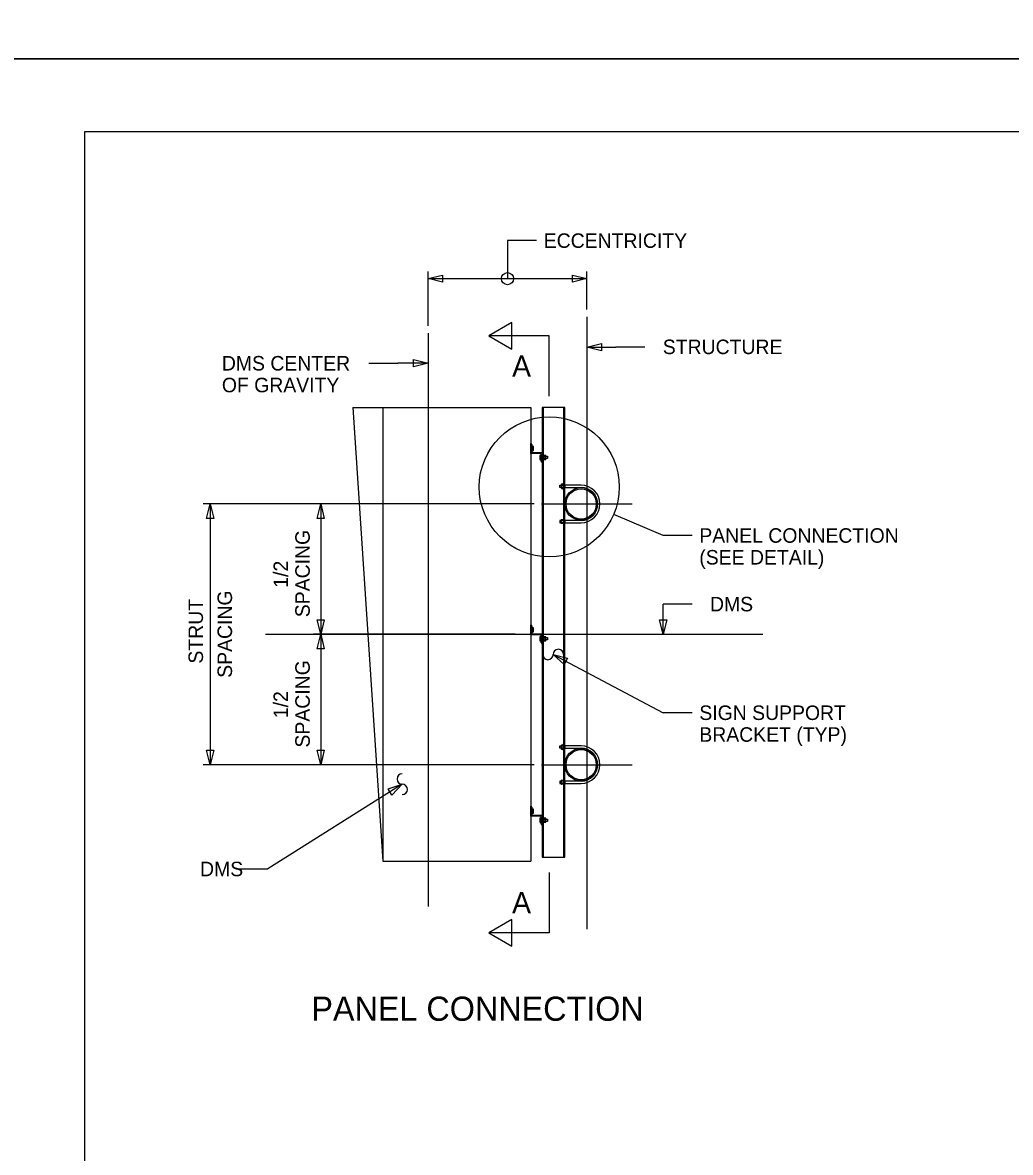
# Model space of a CAD drawing. Extents: x 3829340 to 3831660, y 499389 to 501171.
# Drawn here: x 3830208.1 to 3830412.4, y 499757.1 to 499990.7 of the extents above; entities that cross this region are included whole.
import ezdxf

# ---------------------------------------------------------------- set-up
doc = ezdxf.new("R2010")
doc.units = 0
for name, color, linetype in [('0-ANCHOR', 7, 'Continuous'), ('2', 7, 'Continuous'), ('CNTR', 7, 'Continuous'), ('Default', 7, 'Continuous'), ('DIM TXT', 7, 'Continuous'), ('PLT-BNDY', 7, 'Continuous'), ('sign', 7, 'Continuous'), ('structure', 7, 'Continuous')]:
    doc.layers.add(name, color=color, linetype=linetype)

msp = doc.modelspace()

# ---------------------------------------------------------------- linework, layer by layer
at = {"layer": '0-ANCHOR'}
for p, q in [((3830313.69, 499903.06), (3830313.4, 499903.06)), ((3830313.4, 499903.06), (3830313.4, 499902.23)), ((3830313.69, 499902.85), (3830313.4, 499902.85)), ((3830313.69, 499902.44), (3830313.4, 499902.44)), ((3830313.4, 499902.23), (3830313.69, 499902.23)), ((3830313.74, 499902.28), (3830313.74, 499903.02)), ((3830315.01, 499901.16), (3830315.01, 499900.42)), ((3830315.35, 499901.21), (3830315.06, 499901.21)), ((3830315.06, 499901), (3830315.35, 499901)), ((3830315.35, 499900.38), (3830315.35, 499901.21)), ((3830315.86, 499901.04), (3830315.35, 499901.04)), ((3830316.25, 499901.21), (3830315.86, 499901.21)), ((3830315.86, 499901.21), (3830315.86, 499900.38)), ((3830315.86, 499900.55), (3830315.86, 499901.04)), ((3830315.86, 499901), (3830316.25, 499901)), ((3830316.3, 499900.42), (3830316.3, 499901.16)), ((3830316.3, 499901.04), (3830316.64, 499901.04)), ((3830316.64, 499901.04), (3830316.64, 499900.55)), ((3830315.06, 499900.58), (3830315.35, 499900.58)), ((3830315.06, 499900.38), (3830315.35, 499900.38)), ((3830315.35, 499900.55), (3830315.86, 499900.55)), ((3830315.86, 499900.58), (3830316.25, 499900.58)), ((3830315.86, 499900.38), (3830316.25, 499900.38)), ((3830316.64, 499900.55), (3830316.3, 499900.55)), ((3830313.69, 499865.56), (3830313.4, 499865.56)), ((3830313.4, 499865.56), (3830313.4, 499864.73)), ((3830313.69, 499865.36), (3830313.4, 499865.36)), ((3830313.69, 499864.94), (3830313.4, 499864.94)), ((3830313.4, 499864.73), (3830313.69, 499864.73)), ((3830313.74, 499864.78), (3830313.74, 499865.52)), ((3830315.01, 499863.66), (3830315.01, 499862.92)), ((3830315.35, 499863.71), (3830315.06, 499863.71)), ((3830315.06, 499863.5), (3830315.35, 499863.5)), ((3830315.35, 499862.88), (3830315.35, 499863.71)), ((3830315.86, 499863.54), (3830315.35, 499863.54)), ((3830316.25, 499863.71), (3830315.86, 499863.71)), ((3830315.86, 499863.71), (3830315.86, 499862.88)), ((3830315.86, 499863.05), (3830315.86, 499863.54)), ((3830315.86, 499863.5), (3830316.25, 499863.5)), ((3830316.3, 499862.92), (3830316.3, 499863.66)), ((3830316.3, 499863.54), (3830316.64, 499863.54)), ((3830316.64, 499863.54), (3830316.64, 499863.05)), ((3830315.06, 499863.09), (3830315.35, 499863.09)), ((3830315.06, 499862.88), (3830315.35, 499862.88)), ((3830315.35, 499863.05), (3830315.86, 499863.05)), ((3830315.86, 499863.09), (3830316.25, 499863.09)), ((3830315.86, 499862.88), (3830316.25, 499862.88)), ((3830316.64, 499863.05), (3830316.3, 499863.05)), ((3830313.69, 499828.06), (3830313.4, 499828.06)), ((3830313.4, 499828.06), (3830313.4, 499827.23)), ((3830313.69, 499827.86), (3830313.4, 499827.86)), ((3830313.69, 499827.44), (3830313.4, 499827.44)), ((3830313.4, 499827.23), (3830313.69, 499827.23)), ((3830313.74, 499827.28), (3830313.74, 499828.02)), ((3830315.01, 499826.16), (3830315.01, 499825.43)), ((3830315.35, 499826.21), (3830315.06, 499826.21)), ((3830315.35, 499825.38), (3830315.35, 499826.21)), ((3830316.25, 499826.21), (3830315.86, 499826.21)), ((3830315.86, 499826.21), (3830315.86, 499825.38)), ((3830316.3, 499825.43), (3830316.3, 499826.16)), ((3830315.06, 499826), (3830315.35, 499826)), ((3830315.06, 499825.59), (3830315.35, 499825.59)), ((3830315.06, 499825.38), (3830315.35, 499825.38)), ((3830315.86, 499826.04), (3830315.35, 499826.04)), ((3830315.35, 499825.55), (3830315.86, 499825.55)), ((3830315.86, 499825.55), (3830315.86, 499826.04)), ((3830315.86, 499826), (3830316.25, 499826)), ((3830315.86, 499825.59), (3830316.25, 499825.59)), ((3830315.86, 499825.38), (3830316.25, 499825.38)), ((3830316.3, 499826.04), (3830316.64, 499826.04)), ((3830316.64, 499825.55), (3830316.3, 499825.55)), ((3830316.64, 499826.04), (3830316.64, 499825.55))]:
    msp.add_line(p, q, dxfattribs=at)
for centre, start, end in [((3830313.69, 499903.02), 360, 90), ((3830313.69, 499902.9), 270, 0), ((3830313.69, 499902.39), 360, 90), ((3830313.69, 499902.28), 270, 0), ((3830315.06, 499901.16), 90, 180), ((3830315.06, 499901.05), 180, 270), ((3830316.25, 499901.16), 360, 90), ((3830316.25, 499901.05), 270, 0), ((3830315.06, 499900.54), 90, 180), ((3830315.06, 499900.42), 180, 270), ((3830316.25, 499900.54), 360, 90), ((3830316.25, 499900.42), 270, 0), ((3830313.69, 499865.52), 360, 90), ((3830313.69, 499865.4), 270, 0), ((3830313.69, 499864.89), 360, 90), ((3830313.69, 499864.78), 270, 0), ((3830315.06, 499863.66), 90, 180), ((3830315.06, 499863.55), 180, 270), ((3830316.25, 499863.66), 360, 90), ((3830316.25, 499863.55), 270, 0), ((3830315.06, 499863.04), 90, 180), ((3830315.06, 499862.92), 180, 270), ((3830316.25, 499863.04), 360, 90), ((3830316.25, 499862.92), 270, 0), ((3830313.69, 499828.02), 360, 90), ((3830313.69, 499827.9), 270, 0), ((3830313.69, 499827.39), 360, 90), ((3830313.69, 499827.28), 270, 0), ((3830315.06, 499826.16), 90, 180), ((3830315.06, 499826.05), 180, 270), ((3830316.25, 499826.16), 360, 90), ((3830316.25, 499826.05), 270, 0), ((3830315.06, 499825.54), 90, 180), ((3830315.06, 499825.43), 180, 270), ((3830316.25, 499825.54), 360, 90), ((3830316.25, 499825.43), 270, 0)]:
    msp.add_arc(centre, 0.0469, start, end, dxfattribs=at)
for centre, major_axis, start_param, end_param in [((3830313.69, 499902.73), (0, 0.129), 4.712389, 6.283185), ((3830313.69, 499902.57), (0, -0.129), 0, 1.570796), ((3830315.06, 499900.87), (0, 0.129), 0, 1.570796), ((3830316.25, 499900.87), (0, 0.129), 4.712389, 6.283185), ((3830315.06, 499900.71), (0, -0.129), 4.712389, 6.283185), ((3830316.25, 499900.71), (0, -0.129), 0, 1.570796), ((3830313.69, 499865.23), (0, 0.129), 4.712389, 6.283185), ((3830313.69, 499865.07), (0, -0.129), 0, 1.570796), ((3830315.06, 499863.37), (0, 0.129), 0, 1.570796), ((3830316.25, 499863.37), (0, 0.129), 4.712389, 6.283185), ((3830315.06, 499863.21), (0, -0.129), 4.712389, 6.283185), ((3830316.25, 499863.21), (0, -0.129), 0, 1.570796), ((3830313.69, 499827.73), (0, 0.129), 4.712389, 6.283185), ((3830313.69, 499827.57), (0, -0.129), 0, 1.570796), ((3830315.06, 499825.87), (0, 0.129), 0, 1.570796), ((3830315.06, 499825.72), (0, -0.129), 4.712389, 6.283185), ((3830316.25, 499825.87), (0, 0.129), 4.712389, 6.283185), ((3830316.25, 499825.72), (0, -0.129), 0, 1.570796)]:
    msp.add_ellipse(centre, major_axis=major_axis, ratio=0.362172, start_param=start_param, end_param=end_param, dxfattribs=at)
at = {"layer": '2'}
for p, q in [((3830220.96, 499404.19), (3830220.96, 499968.19)), ((3830220.96, 499968.19), (3831006.96, 499968.19))]:
    msp.add_line(p, q, dxfattribs=at)
at = {"layer": 'CNTR'}
for p, q in [((3830324.77, 499929.84), (3830324.77, 499803.28)), ((3830291.93, 499926.51), (3830291.93, 499807.97)), ((3830315.39, 499891.17), (3830334.14, 499891.17)), ((3830258.31, 499864.22), (3830361.13, 499864.22)), ((3830315.39, 499837.27), (3830334.14, 499837.27))]:
    msp.add_line(p, q, dxfattribs=at)
at = {"layer": 'Default'}
for p, q in [((3830309.25, 499928.69), (3830304.49, 499925.94)), ((3830309.25, 499923.19), (3830309.25, 499928.69)), ((3830304.49, 499925.94), (3830309.25, 499923.19)), ((3830309.25, 499805.25), (3830304.49, 499802.5)), ((3830309.25, 499799.75), (3830309.25, 499805.25)), ((3830304.49, 499802.5), (3830309.25, 499799.75))]:
    msp.add_line(p, q, dxfattribs=at)
at = {"layer": 'DIM TXT'}
for p, q in [((3830308.35, 499945.61), (3830308.35, 499937.75)), ((3830314.35, 499945.61), (3830308.35, 499945.61)), ((3830291.93, 499928.01), (3830291.93, 499939.25)), ((3830324.77, 499931.34), (3830324.77, 499939.25)), ((3830291.93, 499937.75), (3830324.77, 499937.75)), ((3830316.99, 499925.94), (3830304.49, 499925.94)), ((3830316.99, 499913.44), (3830316.99, 499925.94)), ((3830324.77, 499923.59), (3830330.77, 499923.59)), ((3830336.77, 499923.59), (3830330.77, 499923.59)), ((3830279.68, 499920.26), (3830285.68, 499920.26)), ((3830291.93, 499920.26), (3830285.68, 499920.26)), ((3830313.89, 499891.17), (3830245.39, 499891.17)), ((3830246.89, 499891.17), (3830246.89, 499837.27)), ((3830313.89, 499891.17), (3830268.22, 499891.17)), ((3830269.72, 499891.17), (3830269.72, 499864.22)), ((3830340.52, 499884.65), (3830330.31, 499889.01)), ((3830346.52, 499884.65), (3830340.52, 499884.65)), ((3830340.52, 499864.22), (3830340.52, 499870.47)), ((3830346.52, 499870.47), (3830340.52, 499870.47)), ((3830309.91, 499864.22), (3830268.22, 499864.22)), ((3830309.91, 499864.22), (3830268.22, 499864.22)), ((3830269.72, 499864.22), (3830269.72, 499837.27)), ((3830317.79, 499860.05), (3830340.52, 499848.01)), ((3830346.52, 499848.01), (3830340.52, 499848.01)), ((3830313.89, 499837.27), (3830245.39, 499837.27)), ((3830313.89, 499837.27), (3830268.22, 499837.27)), ((3830286.6, 499833.24), (3830258.82, 499815.71)), ((3830252.82, 499815.71), (3830258.82, 499815.71)), ((3830316.99, 499815), (3830316.99, 499802.5)), ((3830316.99, 499802.5), (3830304.49, 499802.5))]:
    msp.add_line(p, q, dxfattribs=at)
for points in [[(3830294.93, 499937), (3830291.93, 499937.75), (3830294.93, 499938.5)], [(3830321.77, 499938.5), (3830324.77, 499937.75), (3830321.77, 499937)], [(3830327.77, 499922.84), (3830324.77, 499923.59), (3830327.77, 499924.34)], [(3830288.93, 499921.01), (3830291.93, 499920.26), (3830288.93, 499919.51)], [(3830246.14, 499888.17), (3830246.89, 499891.17), (3830247.64, 499888.17)], [(3830268.97, 499888.17), (3830269.72, 499891.17), (3830270.47, 499888.17)], [(3830270.47, 499867.22), (3830269.72, 499864.22), (3830268.97, 499867.22)], [(3830341.27, 499867.22), (3830340.52, 499864.22), (3830339.77, 499867.22)], [(3830268.97, 499861.22), (3830269.72, 499864.22), (3830270.47, 499861.22)], [(3830320.09, 499857.98), (3830317.79, 499860.05), (3830320.79, 499859.31)], [(3830247.64, 499840.27), (3830246.89, 499837.27), (3830246.14, 499840.27)], [(3830270.47, 499840.27), (3830269.72, 499837.27), (3830268.97, 499840.27)], [(3830283.67, 499832.27), (3830286.6, 499833.24), (3830284.47, 499831)]]:
    msp.add_lwpolyline(points, close=True, dxfattribs=at)
for centre, radius in [((3830308.35, 499937.75), 1.25), ((3830316.99, 499894.69), 14.48)]:
    msp.add_circle(centre, radius, dxfattribs=at)
for centre, start, end in [((3830318.87, 499860.05), 0, 180), ((3830316.72, 499860.05), 180, 0), ((3830286.6, 499834.31), 90, 270), ((3830286.6, 499832.16), 270, 90)]:
    msp.add_arc(centre, 1.08, start, end, dxfattribs=at)
at = {"layer": 'PLT-BNDY'}
for points in [[(3830180.96, 500577.19), (3831021.96, 500577.19), (3831021.96, 499983.19), (3830180.96, 499983.19)], [(3830180.96, 499983.19), (3831021.96, 499983.19), (3831021.96, 499389.19), (3830180.96, 499389.19)]]:
    msp.add_lwpolyline(points, close=True, dxfattribs=at)
at = {"layer": 'sign'}
for p, q in [((3830276.4, 499911.09), (3830282.55, 499817.35)), ((3830276.4, 499911.09), (3830313.2, 499911.09)), ((3830282.55, 499911.09), (3830282.55, 499817.35)), ((3830313.2, 499911.09), (3830313.2, 499817.35)), ((3830313.2, 499901.62), (3830313.2, 499903.67)), ((3830313.4, 499903.48), (3830313.4, 499902.01)), ((3830315.15, 499901.62), (3830313.2, 499901.62)), ((3830313.59, 499901.82), (3830315.55, 499901.82)), ((3830315.35, 499899.96), (3830315.35, 499901.43)), ((3830315.55, 499901.82), (3830315.55, 499899.77)), ((3830319.15, 499894.57), (3830319.15, 499895.05)), ((3830319.15, 499895.05), (3830319.48, 499895.05)), ((3830319.48, 499894.57), (3830319.15, 499894.57)), ((3830319.48, 499895.18), (3830319.48, 499894.44)), ((3830319.92, 499895.23), (3830319.53, 499895.23)), ((3830319.92, 499895.02), (3830319.53, 499895.02)), ((3830319.92, 499894.6), (3830319.53, 499894.6)), ((3830319.53, 499894.4), (3830319.92, 499894.4)), ((3830319.92, 499894.13), (3830319.92, 499895.49)), ((3830319.92, 499895.49), (3830320.02, 499895.49)), ((3830319.92, 499894.4), (3830319.92, 499895.23)), ((3830320.02, 499894.13), (3830319.92, 499894.13)), ((3830320.02, 499895.49), (3830320.02, 499894.13)), ((3830323.59, 499895.05), (3830320.22, 499895.05)), ((3830320.22, 499895.05), (3830320.22, 499894.57)), ((3830320.22, 499894.57), (3830323.59, 499894.57)), ((3830319.48, 499887.78), (3830319.15, 499887.78)), ((3830319.15, 499887.78), (3830319.15, 499887.29)), ((3830319.15, 499887.29), (3830319.48, 499887.29)), ((3830319.48, 499887.17), (3830319.48, 499887.9)), ((3830319.53, 499887.95), (3830319.92, 499887.95)), ((3830319.92, 499887.74), (3830319.53, 499887.74)), ((3830319.92, 499887.33), (3830319.53, 499887.33)), ((3830319.92, 499887.12), (3830319.53, 499887.12)), ((3830320.02, 499888.22), (3830319.92, 499888.22)), ((3830319.92, 499888.22), (3830319.92, 499886.85)), ((3830319.92, 499887.95), (3830319.92, 499887.12)), ((3830319.92, 499886.85), (3830320.02, 499886.85)), ((3830320.02, 499886.85), (3830320.02, 499888.22)), ((3830323.59, 499887.78), (3830320.22, 499887.78)), ((3830320.22, 499887.78), (3830320.22, 499887.29)), ((3830320.22, 499887.29), (3830323.59, 499887.29)), ((3830313.2, 499864.12), (3830313.2, 499866.17)), ((3830313.4, 499865.98), (3830313.4, 499864.51)), ((3830315.15, 499864.12), (3830313.2, 499864.12)), ((3830313.59, 499864.32), (3830315.55, 499864.32)), ((3830315.35, 499862.46), (3830315.35, 499863.93)), ((3830315.55, 499864.32), (3830315.55, 499862.27)), ((3830319.15, 499840.66), (3830319.15, 499841.15)), ((3830319.15, 499841.15), (3830319.48, 499841.15)), ((3830319.48, 499840.66), (3830319.15, 499840.66)), ((3830319.48, 499841.27), (3830319.48, 499840.54)), ((3830319.92, 499841.32), (3830319.53, 499841.32)), ((3830319.92, 499841.11), (3830319.53, 499841.11)), ((3830319.92, 499840.7), (3830319.53, 499840.7)), ((3830319.53, 499840.49), (3830319.92, 499840.49)), ((3830319.92, 499840.22), (3830319.92, 499841.59)), ((3830319.92, 499841.59), (3830320.02, 499841.59)), ((3830319.92, 499840.49), (3830319.92, 499841.32)), ((3830320.02, 499840.22), (3830319.92, 499840.22)), ((3830320.02, 499841.59), (3830320.02, 499840.22)), ((3830323.59, 499841.15), (3830320.22, 499841.15)), ((3830320.22, 499841.15), (3830320.22, 499840.66)), ((3830320.22, 499840.66), (3830323.59, 499840.66)), ((3830319.48, 499833.87), (3830319.15, 499833.87)), ((3830319.15, 499833.87), (3830319.15, 499833.39)), ((3830319.15, 499833.39), (3830319.48, 499833.39)), ((3830319.48, 499833.26), (3830319.48, 499834)), ((3830319.53, 499834.05), (3830319.92, 499834.05)), ((3830319.92, 499833.84), (3830319.53, 499833.84)), ((3830319.92, 499833.42), (3830319.53, 499833.42)), ((3830319.92, 499833.22), (3830319.53, 499833.22)), ((3830320.02, 499834.31), (3830319.92, 499834.31)), ((3830319.92, 499834.31), (3830319.92, 499832.95)), ((3830319.92, 499834.05), (3830319.92, 499833.22)), ((3830320.02, 499832.95), (3830320.02, 499834.31)), ((3830323.59, 499833.87), (3830320.22, 499833.87)), ((3830320.22, 499833.87), (3830320.22, 499833.39)), ((3830320.22, 499833.39), (3830323.59, 499833.39)), ((3830319.92, 499832.95), (3830320.02, 499832.95)), ((3830313.2, 499826.62), (3830313.2, 499828.67)), ((3830313.4, 499828.48), (3830313.4, 499827.01)), ((3830315.15, 499826.62), (3830313.2, 499826.62)), ((3830313.59, 499826.82), (3830315.55, 499826.82)), ((3830315.35, 499824.96), (3830315.35, 499826.43)), ((3830315.55, 499826.82), (3830315.55, 499824.77)), ((3830282.55, 499817.35), (3830313.2, 499817.35))]:
    msp.add_line(p, q, dxfattribs=at)
for centre, radius, start, end in [((3830313.2, 499903.48), 0.195, 0, 90), ((3830313.59, 499902.01), 0.195, 180, 270), ((3830315.15, 499901.43), 0.195, 0, 90), ((3830315.55, 499899.96), 0.195, 180, 270), ((3830319.53, 499895.18), 0.0469, 90, 180), ((3830319.53, 499895.06), 0.0469, 180, 270), ((3830319.53, 499894.56), 0.0469, 90, 180), ((3830319.53, 499894.44), 0.0469, 180, 270), ((3830323.59, 499891.17), 3.88, 270, 90), ((3830323.59, 499891.17), 3.39, 270, 90), ((3830319.53, 499887.9), 0.0469, 90, 180), ((3830319.53, 499887.79), 0.0469, 180, 270), ((3830319.53, 499887.28), 0.0469, 90, 180), ((3830319.53, 499887.17), 0.0469, 180, 270), ((3830313.2, 499865.98), 0.195, 0, 90), ((3830313.59, 499864.51), 0.195, 180, 270), ((3830315.15, 499863.93), 0.195, 0, 90), ((3830315.55, 499862.46), 0.195, 180, 270), ((3830319.53, 499841.27), 0.0469, 90, 180), ((3830319.53, 499841.16), 0.0469, 180, 270), ((3830319.53, 499840.65), 0.0469, 90, 180), ((3830319.53, 499840.54), 0.0469, 180, 270), ((3830323.59, 499837.27), 3.88, 270, 90), ((3830323.59, 499837.27), 3.39, 270, 90), ((3830319.53, 499834), 0.0469, 90, 180), ((3830319.53, 499833.88), 0.0469, 180, 270), ((3830319.53, 499833.38), 0.0469, 90, 180), ((3830319.53, 499833.26), 0.0469, 180, 270), ((3830313.2, 499828.48), 0.195, 0, 90), ((3830313.59, 499827.01), 0.195, 180, 270), ((3830315.15, 499826.43), 0.195, 0, 90), ((3830315.55, 499824.96), 0.195, 180, 270)]:
    msp.add_arc(centre, radius, start, end, dxfattribs=at)
for centre, major_axis, start_param, end_param in [((3830319.53, 499894.89), (0, 0.129), 0, 1.570796), ((3830319.53, 499894.73), (0, -0.129), 4.712389, 6.283185), ((3830319.53, 499887.61), (0, 0.129), 0, 1.570796), ((3830319.53, 499887.46), (0, -0.129), 4.712389, 6.283185), ((3830319.53, 499840.98), (0, 0.129), 0, 1.570796), ((3830319.53, 499840.83), (0, -0.129), 4.712389, 6.283185), ((3830319.53, 499833.71), (0, 0.129), 0, 1.570796), ((3830319.53, 499833.55), (0, -0.129), 4.712389, 6.283185)]:
    msp.add_ellipse(centre, major_axis=major_axis, ratio=0.362172, start_param=start_param, end_param=end_param, dxfattribs=at)
at = {"layer": 'structure'}
for p, q in [((3830320.22, 499911.09), (3830315.55, 499911.09)), ((3830315.55, 499911.09), (3830315.55, 499818.13)), ((3830320.02, 499911.09), (3830315.75, 499911.09)), ((3830315.75, 499911.09), (3830315.75, 499818.13)), ((3830320.02, 499818.13), (3830320.02, 499911.09)), ((3830320.22, 499818.13), (3830320.22, 499911.09)), ((3830315.55, 499818.13), (3830320.22, 499818.13)), ((3830315.75, 499818.13), (3830320.02, 499818.13))]:
    msp.add_line(p, q, dxfattribs=at)
for centre, radius in [((3830323.59, 499891.17), 3.37), ((3830323.59, 499891.17), 3.12), ((3830323.59, 499837.27), 3.37), ((3830323.59, 499837.27), 3.12)]:
    msp.add_circle(centre, radius, dxfattribs=at)

# ---------------------------------------------------------------- texts
at = {"layer": 'Default'}
msp.add_text('PANEL CONNECTION', height=4.9999, dxfattribs=at).set_placement((3830267.8, 499784.32))
at = {"layer": 'DIM TXT'}
for s, height, p in [('ECCENTRICITY', 2.9999, (3830315.85, 499944.11)), ('  STRUCTURE', 2.9999, (3830338.24, 499922.15)), ('DMS CENTER', 3, (3830249.29, 499918.76)), ('A', 4.37, (3830309.31, 499917.5)), ('OF GRAVITY', 3, (3830249.29, 499914.26)), ('PANEL CONNECTION', 2.9999, (3830348.02, 499883.15)), ('(SEE DETAIL)', 2.9999, (3830348.02, 499878.65)), ('  DMS', 3, (3830348, 499868.97)), ('SIGN SUPPORT ', 2.9999, (3830348.02, 499846.51)), ('BRACKET (TYP)', 2.9999, (3830348.02, 499842.01)), ('DMS', 3, (3830244.78, 499814.21)), ('A', 4.37, (3830309.31, 499806.57))]:
    msp.add_text(s, height=height, dxfattribs=at).set_placement(p)
for s, p in [('SPACING', (3830267.47, 499867.76)), ('1/2', (3830262.97, 499873.85)), ('SPACING', (3830251.39, 499855.23)), ('STRUT', (3830245.39, 499858.17)), ('SPACING', (3830267.47, 499840.81)), ('1/2', (3830262.97, 499846.89))]:
    msp.add_text(s, height=3, rotation=90, dxfattribs=at).set_placement(p)

doc.saveas('drawing.dxf')
